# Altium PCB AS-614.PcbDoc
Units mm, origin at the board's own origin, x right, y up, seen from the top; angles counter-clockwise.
Board outline 32 x 30 mm, 4 copper layers (Top Layer, Layer 1, Layer 2, Bottom Layer), stack 0.98 mm thick; 51 components, 41 nets, 241 pads, 105 vias.
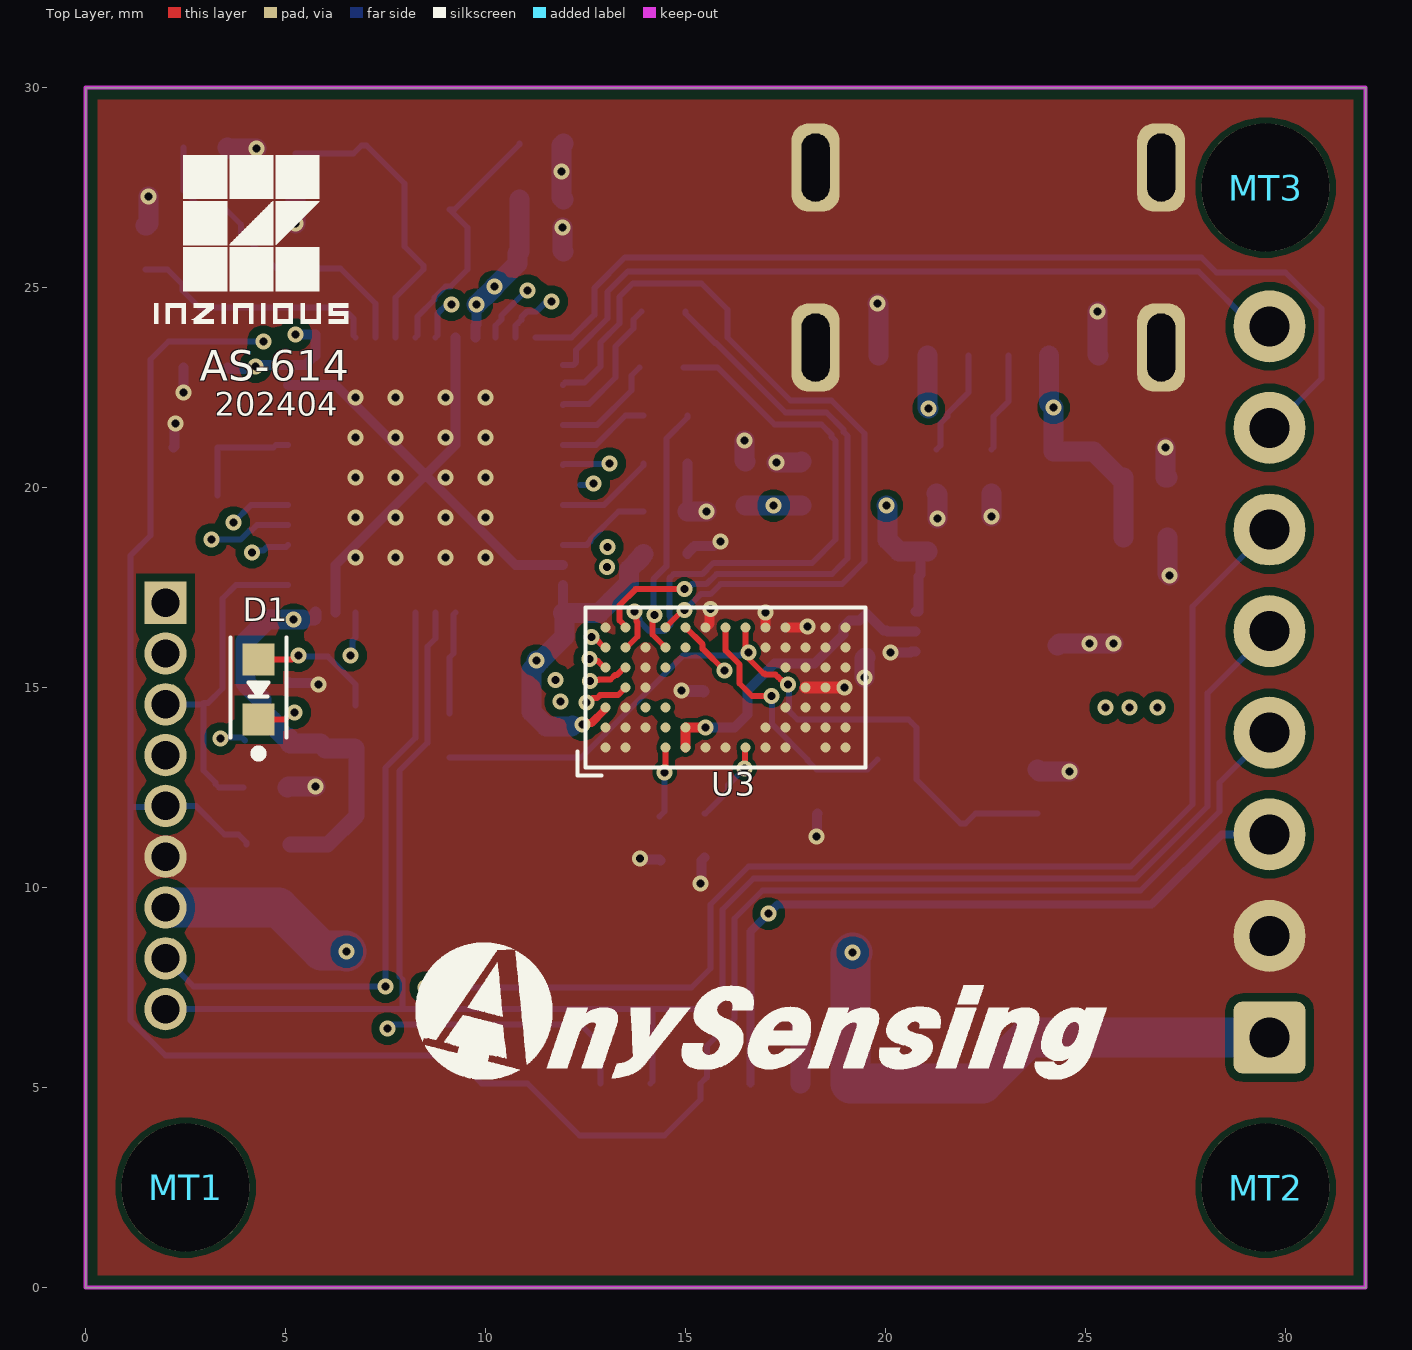
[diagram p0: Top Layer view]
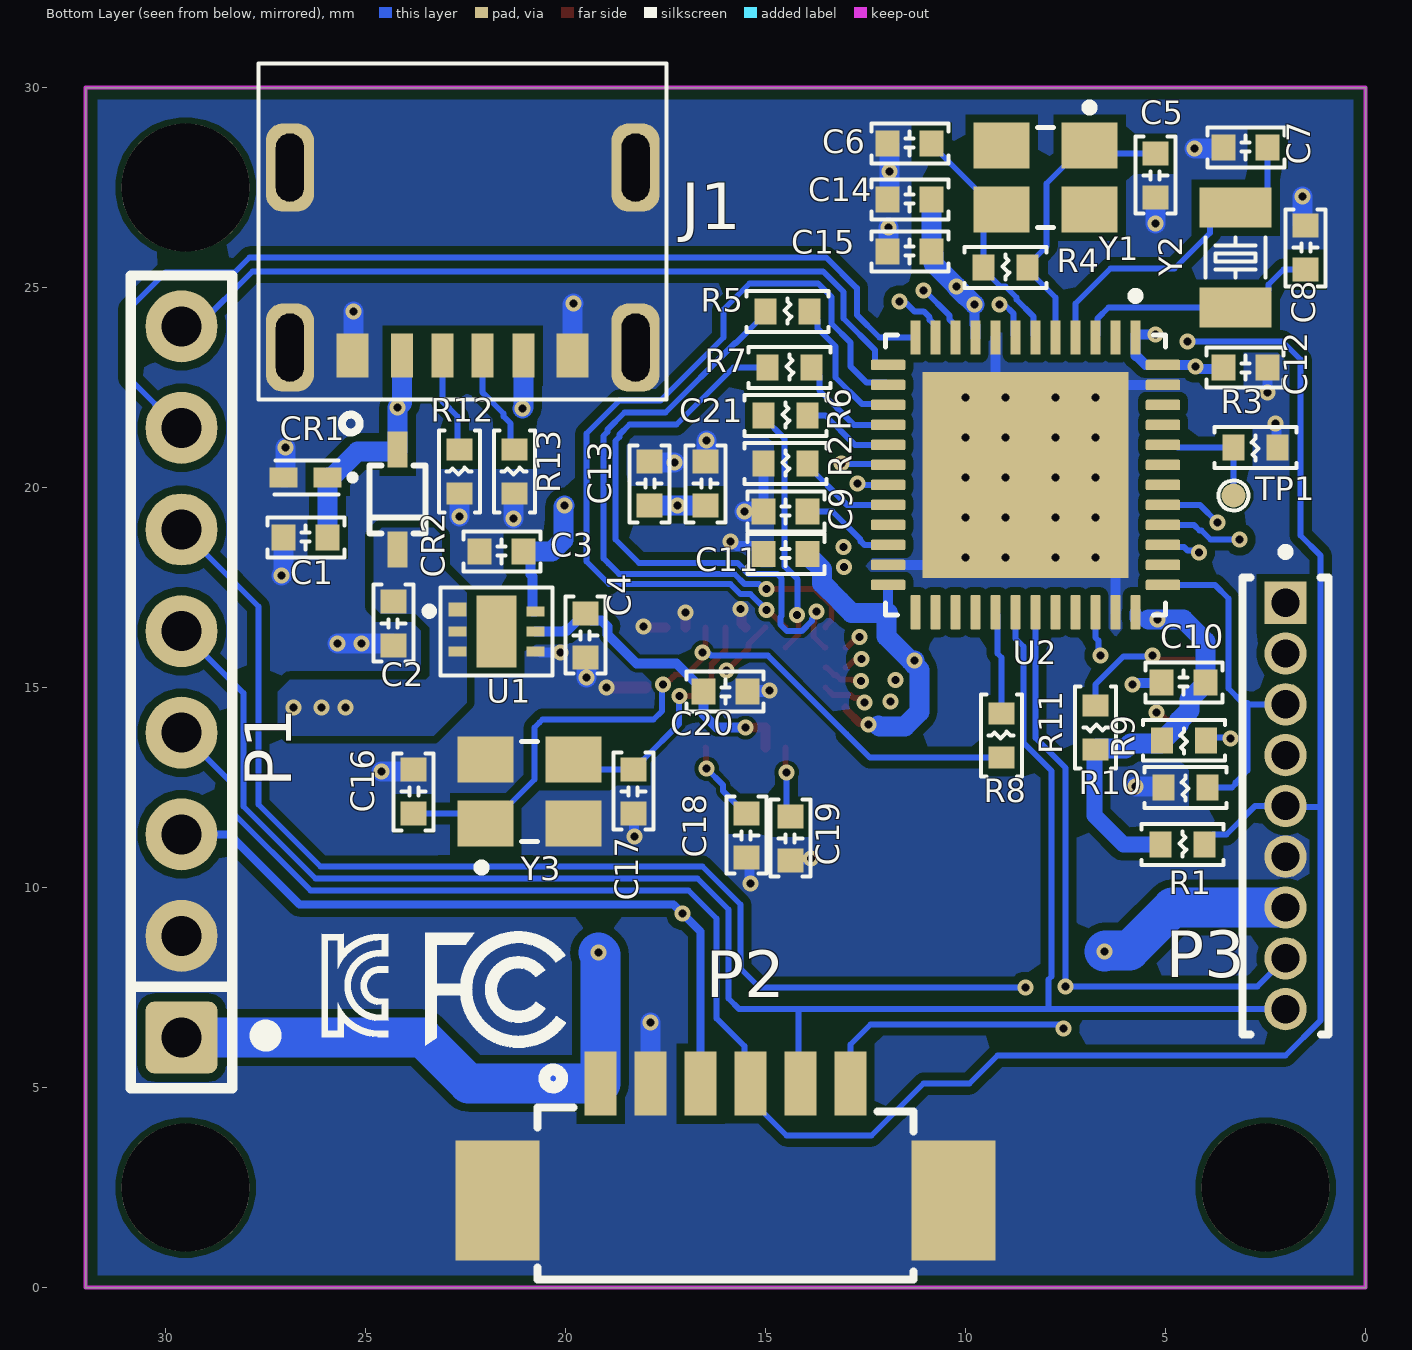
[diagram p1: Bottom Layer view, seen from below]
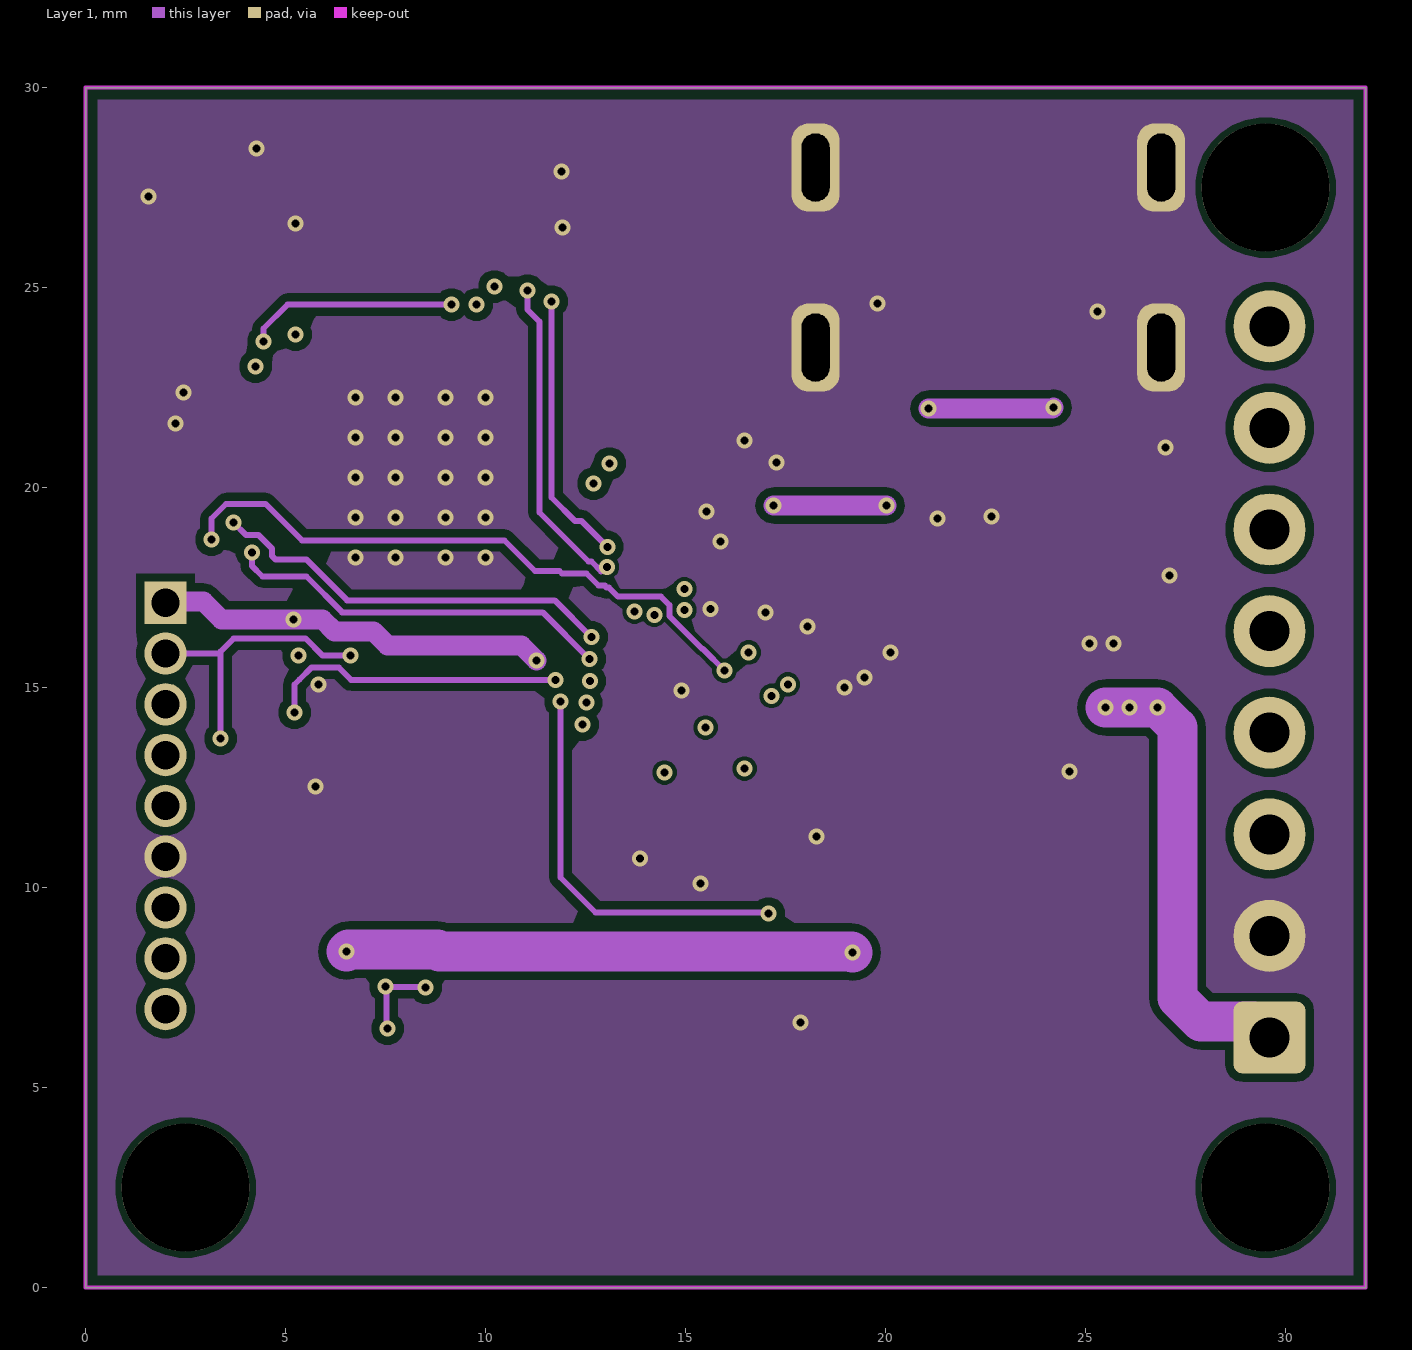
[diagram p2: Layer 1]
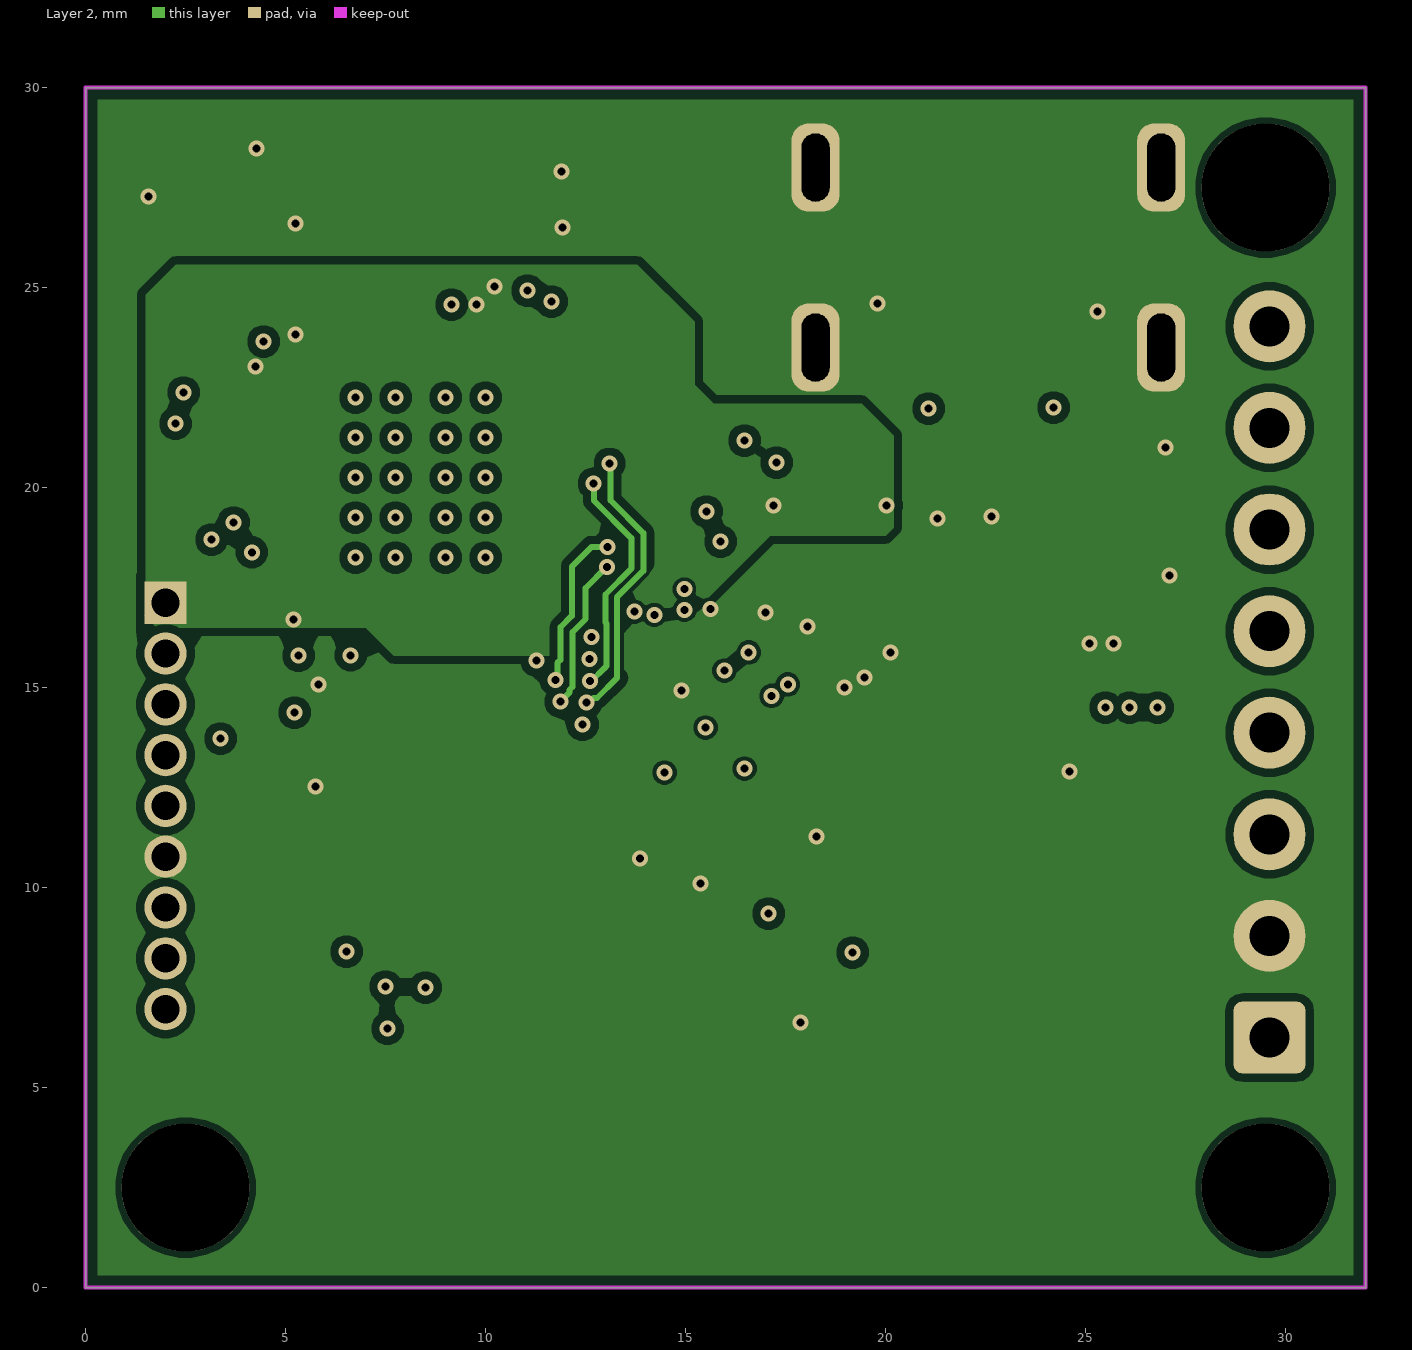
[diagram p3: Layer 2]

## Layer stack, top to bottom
Top Solder: solder mask 0.0102, Solder Resist, Dk 3.5
Top Layer: signal copper 0.0356
Dielectric 2: prepreg 0.0711, PP-006, Dk 4.1
Layer 1: signal copper 0.035
Dielectric 1: dielectric 0.697, FR-4, Dk 4.8
Layer 2: signal copper 0.035
Dielectric 3: prepreg 0.0711, PP-006, Dk 4.1
Bottom Layer: signal copper 0.0356
Bottom Solder: solder mask 0.0102, Solder Resist, Dk 3.5

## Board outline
0,0 0,30 32,30 32,0

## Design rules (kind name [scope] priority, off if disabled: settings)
AssemblyTestPointUsage [All] p1 off:
AssemblyTestpoint [All] p1 off: testpointundercomponent=TRUE minsize=1.016 maxsize=2.54 preferedsize=1.524 minholesize=0 maxholesize=1.016 preferedholesize=0.813 testpointgrid=0.025 usegrid=TRUE gridtolerance=0 allowsidetop=TRUE allowsidebottom=TRUE
BoardOutlineClearance BoardOutlineClearance_1 [OnLayer('Layer 2')] p1 off: gap=0.7 ignorepadtopadclearanceinfootprint=FALSE
BoardOutlineClearance [All] p2: gap=0.3 ignorepadtopadclearanceinfootprint=FALSE
Clearance Clearance_BGA [WithinRoom('BGA')] p1: gap=0.1 ignorepadtopadclearanceinfootprint=TRUE
Clearance [All] p2: gap=0.15 ignorepadtopadclearanceinfootprint=TRUE except(0.2: Arc-Fill Arc-Poly Arc-Region Track-Fill Track-Poly Track-Region SMDPad-Fill SMDPad-Poly SMDPad-Region THPad-Fill THPad-Poly THPad-Region Via-Fill Via-Poly Via-Region Fill-Fill Fill-Poly Fill-Region Poly-Poly Poly-Region Region-Region)
ComponentClearance [All] p1 off: gap=0.254 collisioncheckmode=3 verticalgap=0.254 showdistances=FALSE
DiffPairsRouting [All] p1: maxlimit=0.254 minlimit=0.1 mostfreqgap=0.1 toplayer_minwidth=0.17 toplayer_maxwidth=0.381 toplayer_prefwidth=0.17 midlayer1_minwidth=0.17 midlayer1_maxwidth=0.381 midlayer1_prefwidth=0.17 midlayer2_minwidth=0.17 midlayer2_maxwidth=0.381 midlayer2_prefwidth=0.17 bottomlayer_minwidth=0.17 bottomlayer_maxwidth=0.381 bottomlayer_prefwidth=0.17 maxuncoupledlength=12.7
FabricationTestPointUsage [All] p1 off: valid=0 allowmultiple=FALSE
FabricationTestpoint [All] p1 off: side=3 testpointundercomponent=TRUE minsize=1.016 maxsize=2.54 preferedsize=1.524 minholesize=0 maxholesize=1.016 preferedholesize=0.813 testpointgrid=0.025 allowsidetop=TRUE allowsidebottom=TRUE usegrid=TRUE gridtolerance=0
Height [All] p1 off: minheight=0 maxheight=25.4 prefheight=12.7
HoleSize [All] p1 off: absolutevalues=TRUE maxlimit=2.54 minlimit=0.025 maxpercent=80.000 minpercent=20.000
HoleToHoleClearance [All] p1 off: gap=0.254 allowstackedmicrovias=TRUE
LayerPairs [All] p1 off: enforce=TRUE
MinimumSolderMaskSliver [All] p1 off: minsoldermaskwidth=0.254
NetAntennae [All] p1 off: netantennaetolerance=0
PolygonConnect [All] p1: connectstyle=Direct reliefconductorwidth=0.254 reliefentries=4 polygonreliefangle="90 Angle" airgapwidth=0.254
RoomDefinition BGA [False] p1: confinementstyle=ConfineIn formatcopy=TRUE lockcomponents=FALSE outline 12.981,18.1 19,18.1 19,11.968 12.981,11.968
RoutingVias [All] p1: holewidth=0.711 width=1.27 viastyle="Through Hole" minholewidth=0.711 minwidth=1.27 maxholewidth=0.711 maxwidth=1.27 useviatemplates=TRUE viatemplateguid#1={A169AA66-EAF8-4FBB-931A-80E976BA8041} viatemplatename#1=v40h20m0mx0
SilkToSilkClearance [All] p1 off: silktosilkclearance=0.254
SilkToSolderMaskClearance [IsPad] p1 off: minsilkscreentomaskgap=0.254 clearancetoexposedcopper=TRUE
SolderMaskExpansion [All] p1: expansion=0.102 istentingtop=FALSE
SupplyNets "Schematic Supply Nets_3" [InNet('VCC_3V3')] p1: voltage=0.000
SupplyNets "Schematic Supply Nets_2" [InNet('GND')] p2: voltage=0.000
SupplyNets "Schematic Supply Nets_1" [InNet('VCC_1V8')] p3: voltage=0.000
SupplyNets "Schematic Supply Nets" [InNet('VCC_EXT')] p4: voltage=0.000
Width [All] p1: maxlimit=3 minlimit=0.15 preferedwidth=0.15
16 further rules are at their usual default settings.

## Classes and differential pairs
component class AS-614: C1 C2 C3 C4 C5 C6 C7 C8 C9 C10 C11 C12 C13 C14 C15 C16 C17 C18 C19 C20 C21 CR1 CR2 D1 J1 P1 P2 P3 R1 R2 R3 R4 R5 R6 R7 R8 R9 R10 R11 R12 R13 TP1 U1 U2 U3 Y1 Y2 Y3

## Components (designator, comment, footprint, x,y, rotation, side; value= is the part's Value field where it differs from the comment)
C1 "Cap Semi" "CAP 0402/1005" 26.5,18.75 r180 bottom value=1uF
C2 "Cap Semi" "CAP 0402/1005" 24.3,16.6 r90 bottom value=1uF
C3 "Cap Semi" "CAP 0402/1005" 21.6,18.4 r180 bottom value=1uF
C4 "Cap Semi" "CAP 0402/1005" 19.5,16.3 r90 bottom value=1uF
C5 "Cap Semi" "CAP 0402/1005" 5.25,27.8 r90 bottom value=20pF
C6 "Cap Semi" "CAP 0402/1005" 11.4,28.6 r180 bottom value=20pF
C7 "Cap Semi" "CAP 0402/1005" 3,28.5 r180 bottom value=10pF
C8 "Cap Semi" "CAP 0402/1005" 1.5,26 r270 bottom value=10pF
C9 "Cap Semi" "CAP 0402/1005" 14.5,19.4 r180 bottom value=4.7uF
C10 "Cap Semi" "CAP 0402/1005" 4.55,15.125 r180 bottom value=100nF
C11 "Cap Semi" "CAP 0402/1005" 14.495,18.333 r180 bottom value=100nF
C12 "Cap Semi" "CAP 0402/1005" 3,23 r0 bottom value=100nF
C13 "Cap Semi" "CAP 0402/1005" 17.9,20.1 r270 bottom value=4.7uF
C14 "Cap Semi" "CAP 0402/1005" 11.4,27.2 r180 bottom value=100nF
C15 "Cap Semi" "CAP 0402/1005" 11.4,25.9 r180 bottom value=1uF
C16 "Cap Semi" "CAP 0402/1005" 23.8,12.4 r270 bottom value=8pF
C17 "Cap Semi" "CAP 0402/1005" 18.3,12.4 r90 bottom value=8pF
C18 "Cap Semi" "CAP 0402/1005" 15.475,11.3 r90 bottom value=1uF
C19 "Cap Semi" "CAP 0402/1005" 14.375,11.225 r90 bottom value=1uF
C20 "Cap Semi" "CAP 0402/1005" 16,14.9 r0 bottom value=470nF
C21 "Cap Semi" "CAP 0402/1005" 16.5,20.1 r270 bottom value=220nF
CR1 "LESD5D5.0CT1G" SOD523 26.5,20.25 r180 bottom
CR2 "BAT760Q-7" "SOD-323 - 21" 24.2,19.7 r270 bottom
D1 "LED2" "LED 0603/1608 RED" 4.325,14.95 r270 top
J1 "TYPE-C-31-M-17" CON/USB-C/6P-1 22.57,23.5 r0 bottom locked
MT1 "MOUNT HOLE" "MT-3 /HOLE" 2.5,2.5 r0 top locked
MT2 "MOUNT HOLE" "MT-3 /HOLE" 29.5,2.5 r0 top
MT3 "MOUNT HOLE" "MT-3 /HOLE" 29.5,27.5 r0 top locked
P1 "EXT_IO1/2.54mm" "Pin Header 1x8 TH Pitch 2.54mm" 29.6,6.25 r90 bottom locked
P2 "EXT_IO2/12505WR-06" 12505WR-06/53261-0671 16,5.1 r180 bottom locked
P3 "Debug/1.27mm" "PIN HEADER 1X9 TH 1.27mm" 2,12.04 r270 bottom
R1 "Res3" "RES 0402/1005" 4.575,11.075 r0 bottom value=10K
R2 "Res3" "RES 0402/1005" 14.5,20.6 r0 bottom value=10K
R3 "Res3" "RES 0402/1005" 2.75,21 r180 bottom value=10K
R4 "Res3" "RES 0402/1005" 9,25.5 r0 bottom value=1M
R5 "Res3" "RES 0402/1005" 14.45,24.4 r0 bottom value=33R
R6 "Res3" "RES 0402/1005" 14.5,21.8 r0 bottom value=33R
R7 "Res3" "RES 0402/1005" 14.4,23 r0 bottom value=33R
R8 "Res3" "RES 0402/1005" 9.1,13.8 r270 bottom value=0R
R9 "Res3" "RES 0402/1005" 4.532,13.681 r180 bottom value=10K
R10 "Res3" "RES 0402/1005" 4.5,12.5 r180 bottom value=10K
R11 "Res3" "RES 0402/1005" 6.75,14 r90 bottom value=330R
R12 "Res3" "RES 0402/1005" 22.65,20.4 r270 bottom value=5.1K
R13 "Res3" "RES 0402/1005" 21.275,20.4 r270 bottom value=5.1K
TP1 "BOOT" "TP/0.6 / SMD" 3.3,19.8 r180 bottom
U1 "VRD1833MLX" "LLP-6 / L2.0-W1.8-P0.50-BL-EP" 21.725,16.425 r270 bottom
U2 "APM32F411CEU6" "VQFN-48/ QFN50P700X700X100-49N" 8.5,20.315 r270 bottom
U3 "SC1240AR3" "BGA62 7X4" 16,15 r90 top locked
Y1 "CRYSTAL13" XTAL_3225 8,27.75 r0 bottom value=8MHz
Y2 "CRYSTAL13" XTAL/3215 3.25,25.75 r270 bottom value=32.768KHz
Y3 "CRYSTAL13" XTAL_3225 20.9,12.4 r180 bottom value=40MHz

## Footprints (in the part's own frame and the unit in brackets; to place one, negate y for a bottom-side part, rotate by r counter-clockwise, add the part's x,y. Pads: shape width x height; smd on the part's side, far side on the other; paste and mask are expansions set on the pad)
12505WR-06/53261-0671 [mm]
  rect 0.8x1.6 smd: 1(-3.125,0) 2(-1.875,0) 3(-0.625,0) 4(0.625,0) 5(1.875,0) 6(3.125,0)
  rect 2.1x3 smd: H(-5.7,-2.925) H(5.7,-2.925)
  silkscreen extent -4.7,-4.9 4.7,0.35, body extent -6.39,-4.75 6.26,0.45, height 3.4
"BGA62 7X4" [mm]
  round 0.25 smd mask+0.05: A1(-1.5,3) A2(-1,3) A3(-0.5,3) A5(0.5,3) A6(1,3) A7(1.5,3) B1(-1.5,2.5) B2(-1,2.5) B3(-0.5,2.5) B4(0,2.5) B5(0.5,2.5) B6(1,2.5) B7(1.5,2.5) C2(-1,2) C3(-0.5,2) C4(0,2) C5(0.5,2) C6(1,2) D1(-1.5,1.5) D2(-1,1.5) D3(-0.5,1.5) D5(0.5,1.5) D6(1,1.5) D7(1.5,1.5) E1(-1.5,1) E2(-1,1) E6(1,1) E7(1.5,1) F1(-1.5,0.5) F7(1.5,0.5) G1(-1.5,0) G7(1.5,0) H1(-1.5,-0.5) H7(1.5,-0.5) J1(-1.5,-1) J2(-1,-1) J6(1,-1) J7(1.5,-1) K1(-1.5,-1.5) K2(-1,-1.5) K3(-0.5,-1.5) K5(0.5,-1.5) K6(1,-1.5) K7(1.5,-1.5) L2(-1,-2) L3(-0.5,-2) L4(0,-2) L5(0.5,-2) L6(1,-2) M1(-1.5,-2.5) M2(-1,-2.5) M3(-0.5,-2.5) M4(0,-2.5) M5(0.5,-2.5) M6(1,-2.5) M7(1.5,-2.5) N1(-1.5,-3) N2(-1,-3) N3(-0.5,-3) N5(0.5,-3) N6(1,-3) N7(1.5,-3)
  silkscreen extent -2.2,-3.5 2,3.7, body extent -2.02,-3.5 2,3.5, height 1.2
"CAP 0402/1005" [mm] "Chip Capacitor, 2-Leads, Body 1.02x0.51mm, IPC Medium Density"
  rect 0.6x0.65 smd: 1(-0.55,0) 2(0.55,0)
  silkscreen extent -0.95,-0.5 0.97,0.5, body extent -0.5,-0.26 0.5,0.26, height 0.52
CON/USB-C/6P-1 [mm]
  rect 0.55x1.1 smd: A5(-0.5,0.2) A9(1.52,0.2) B5(0.5,0.2) B9(-1.52,0.2)
  rect 0.8x1.1 smd: A12(2.75,0.2) B12(-2.75,0.2)
  rrect70% 1.2x2.2 hole 0.7 slot 1.7 at 90 deg: MP(-4.32,-4.5) MP(-4.32,0) MP(4.32,-4.5) MP(4.32,0)
  silkscreen extent -5.1,-7.1 5.1,2.12, body extent -4.47,-6.7 4.47,0.2, height 3.26
"LED 0603/1608 RED" [mm] "Chip Diode, 2-Leads, Body 1.60x0.80mm, IPC Medium Density"
  rect 0.8x0.8 smd: 1(-0.75,0) 2(0.75,0)
  silkscreen extent -1.3,-0.7 1.65,0.7, body extent -0.8,-0.4 0.8,0.4, height 0.53
"LLP-6 / L2.0-W1.8-P0.50-BL-EP" [mm]
  rect 0.35x0.45 smd paste+0 mask+0.051: 1(-0.525,-0.975)
  rect 0.25x0.45 smd paste+0 mask+0.051: 2(0.025,-0.975) 3(0.525,-0.975) 4(0.525,0.975) 5(0.025,0.975) 6(-0.475,0.975)
  rect 1.8x1 smd paste+0 mask+0.051: 7(0.025,0)
  silkscreen extent -1.07,-1.74 1.12,1.4, body extent -0.9,-1 0.9,1, height 0.6
"MT-3 /HOLE" [mm] "Mount Hole 4mm"
  round 3.2 hole 3.2 unplated mask+0: 1(0,0)
"Pin Header 1x8 TH Pitch 2.54mm" [mm] "PinHeader 1x8 TH Pitch 2.54mm"
  rrect25% 1.8x1.8 hole 1: 1(0,0)
  round 1.8 hole 1: 2(2.54,0) 3(5.08,0) 4(7.62,0) 5(10.16,0) 6(12.7,0) 7(15.24,0) 8(17.78,0)
  silkscreen extent -1.27,-2.25 19.05,1.27
"PIN HEADER 1X9 TH 1.27mm" [mm]
  rect 1.06x1.06 hole 0.71: 1(-5.08,0)
  round 1.06 hole 0.71: 2(-3.81,0) 3(-2.54,0) 4(-1.27,0) 5(0,0) 6(1.27,0) 7(2.54,0) 8(3.81,0) 9(5.08,0)
  silkscreen extent -6.45,-1.08 5.71,1.08
"RES 0402/1005" [mm] "Chip Resistor, 2-Leads, Body 1.0x0.5mm, IPC Medium Density"
  rect 0.55x0.65 smd: 1(-0.55,0) 2(0.55,0)
  silkscreen extent -1.02,-0.51 1.02,0.51, body extent -0.5,-0.25 0.5,0.25, height 0.35
SOD523 [mm]
  rect 0.7x0.5 smd: 1(0.55,0) 2(-0.55,0)
  silkscreen extent -0.77,-0.43 1.22,0.43, body extent -0.77,-0.4 0.83,0.4, height 0.65
"SOD-323 - 21" [mm]
  rect 0.9x0.5 smd: 1(1.25,0) 2(-1.25,0)
  silkscreen extent -0.85,-0.7 0.85,0.7, body extent -1.34,-0.66 1.34,0.64, height 1.15
"TP/0.6 / SMD" [mm]
  round 0.6 smd: 1(0,0)
  silkscreen extent -0.38,-0.38 0.37,0.38
"VQFN-48/ QFN50P700X700X100-49N" [mm]
  rrect25% 0.86x0.26 smd: 1(-3.435,2.75) 2(-3.435,2.25) 3(-3.435,1.75) 4(-3.435,1.25) 5(-3.435,0.75) 6(-3.435,0.25) 7(-3.435,-0.25) 8(-3.435,-0.75) 9(-3.435,-1.25) 10(-3.435,-1.75) 11(-3.435,-2.25) 12(-3.435,-2.75) 25(3.435,-2.75) 26(3.435,-2.25) 27(3.435,-1.75) 28(3.435,-1.25) 29(3.435,-0.75) 30(3.435,-0.25) 31(3.435,0.25) 32(3.435,0.75) 33(3.435,1.25) 34(3.435,1.75) 35(3.435,2.25) 36(3.435,2.75)
  rrect25% 0.26x0.86 smd: 13(-2.75,-3.435) 14(-2.25,-3.435) 15(-1.75,-3.435) 16(-1.25,-3.435) 17(-0.75,-3.435) 18(-0.25,-3.435) 19(0.25,-3.435) 20(0.75,-3.435) 21(1.25,-3.435) 22(1.75,-3.435) 23(2.25,-3.435) 24(2.75,-3.435) 37(2.75,3.435) 38(2.25,3.435) 39(1.75,3.435) 40(1.25,3.435) 41(0.75,3.435) 42(0.25,3.435) 43(-0.25,3.435) 44(-0.75,3.435) 45(-1.25,3.435) 46(-1.75,3.435) 47(-2.25,3.435) 48(-2.75,3.435)
  rect 5.15x5.15 smd paste-4: 49(0,0)
  silkscreen extent -4.57,-3.5 3.5,3.5, body extent -3.5,-3.5 3.5,3.5, height 1
XTAL/3215 [mm]
  rect 1x1.8 smd: 1(-1.25,0) 2(1.25,0)
  silkscreen extent -0.5,-0.75 0.5,0.75, body extent -1.6,-0.75 1.6,0.75, height 0.8
XTAL_3225 [mm]
  rect 1.4x1.15 smd: 1(-1.1,-0.8) 2(1.1,-0.8) 3(1.1,0.8) 4(-1.1,0.8)
  silkscreen extent -1.2,-1.85 0.2,1.25, body extent -1.6,-1.25 1.6,1.25, height 1

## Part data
C1 C2 C3 C4 C5 C6 C7 C8 C9 C10 C11 C12 C13 C14 C15 C16 C17 C18 C19 C20 C21: "Capacitor (Semiconductor SIM Model)"
CR1: "No Description Available", Mfr_Name="UMW(Youtai Semiconductor Co., Ltd.)"
CR2: "No Description Available", Mfr_Name="Diodes Inc"
D1: "Typical RED, GREEN, YELLOW, AMBER GaAs LED"
J1: library part CON/USB-C/6P, "6P C-type Connector"
MT1 MT2 MT3: library part "Mount Bolt"
P1: library part "Header 8", "Header, 8-Pin"
P2: library part "Header 6", "Header, 6-Pin"
P3: library part "Header 9", "Header, 9-Pin"
R1 R2 R3 R4 R5 R6 R7 R8 R9 R10 R11 R12 R13: "Resistor"
TP1: library part TP, "Test Point", Color=Red, Manufacturer=Keystone, Supplier Part Number 1=36-5010-ND

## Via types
v1: diameter 0.4, hole 0.2, Top Layer to Bottom Layer, tented both sides, 105 vias

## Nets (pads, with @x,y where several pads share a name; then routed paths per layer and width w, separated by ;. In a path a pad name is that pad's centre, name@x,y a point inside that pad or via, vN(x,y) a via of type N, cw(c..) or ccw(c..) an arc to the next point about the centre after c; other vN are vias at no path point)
GND: C1.1 C2.1 C3.1 C4.1 C5.1 C6.1 C7.1 C8.1 C9.1 C10.1 C11.1 C12.1 C13.1 C14.1 C15.1 C16.1 C17.1 C18.1 C19.1 C20.1 C21.1 CR1.2 J1.A12 J1.B12 J1.MP P1.2 P2.2 P2.H P3.6 R2.2 R3.2 R10.1 R12.2 R13.2 U1.4 U2.8 U2.23 U2.35 U2.47 U2.49 U3.A1 U3.A2 U3.A7 U3.B1 U3.B2 U3.B3 U3.C2 U3.C4 U3.C5 U3.C6 U3.F1 U3.F7 U3.G1 U3.J1 U3.J2 U3.J6 U3.J7 U3.K1 U3.K2 U3.K3 U3.K5 U3.K6 U3.K7 U3.L2 U3.L3 U3.L4 U3.L5 U3.L6 U3.M1 U3.M2 U3.M3 U3.M4 U3.M5 U3.M6 U3.M7 U3.N1 U3.N2 U3.N3 U3.N5 U3.N6 U3.N7 Y3.2 Y3.4 | length 42.7
  Top Layer w0.25: U3.F7 15.597,16.597 15.597,16.93 v1(15.625,16.958) ; U3.J7 v1(17,16.875) ; U3.K7 18.025,16.5 v1(18.05,16.525) v1@18.025,16.55
  Top Layer w0.3: U3.L4 U3.M4 v1(18.975,15)
  Bottom Layer w0.25: R3.2 2.225,21.025 2.225,21.575 v1(2.25,21.6) ; v1(2.45,22.375) C12.1 ; U2.47 6.25,22.565 U2.49 ; C10.1 5.113,15.112 5.739,15.112 5.781,15.071 v1(5.821,15.071) ; U2.35 6.25,18.065 U2.49 ; U2.8 9.25,21.065 U2.49 ; U2.23 10.75,18.065 U2.49 ; v1(13.868,10.725) 13.892,10.7 14.35,10.7 C19.1 ; C11.1 15.045,18.358 15.22,18.533 15.718,18.533 15.834,18.65 v1(15.875,18.65) ; C9.1 R2.2 ; v1(15.375,10.1) 15.404,10.129 15.404,10.679 C18.1 ; v1(18.275,11.275) 18.287,11.287 18.287,11.838 C17.1 ; v1(20.125,15.875) 20.625,15.875 20.65,15.9 U1.4
  Bottom Layer w0.3: v1(14.9,14.925) 14.913,14.913 15.438,14.913 C20.1
  Bottom Layer w0.5: C8.1 1.525,26.55 1.575,26.6 v1(1.575,27.275) ; C7.1 3.575,28.475 v1(4.275,28.475) ; R10.1 5.075,12.525 v1(5.75,12.525) ; v1(5.25,26.6) C5.1 ; v1(11.925,26.5) 11.925,25.925 C15.1 ; C14.1 11.9,27.25 11.9,28.55 C6.1 ; C9.1 v1(15.526,19.4) ; v1(16.476,21.174) 16.476,20.674 C21.1 ; v1(17.275,20.625) 17.875,20.625 C13.1 ; P2.2 v1(17.875,6.625) ; v1(19.475,15.25) 19.475,15.725 C4.1 ; v1(19.8,24.6) 19.82,24.58 J1.B12 ; R13.2 21.3,19.825 v1(21.3,19.225) ; v1(22.65,19.275) R12.2 ; C16.1 23.85,12.9 v1(24.6,12.9) ; C2.1 24.35,16.1 v1(25.1,16.1) v1(25.7,16.1) ; v1(25.3,24.4) 25.3,23.32 J1.A12 ; v1(27,21) 27,20.25 CR1.2 ; C1.1 27.05,17.85 v1(27.1,17.8)
  other v1: 6.75,18.25 7.75,18.25 9,18.25 10,18.25 6.75,19.25 7.75,19.25 9,19.25 10,19.25 6.75,20.25 7.75,20.25 9,20.25 10,20.25 6.75,21.25 7.75,21.25 9,21.25 10,21.25 6.75,22.25 7.75,22.25 9,22.25 10,22.25 11.9,27.9
NetC1_2: C1.2 CR1.1 CR2.2 J1.A9 J1.B9 | length 10.4
  Layer 1 w0.5: v1(21.075,21.975) 24.175,21.975 v1(24.2,22)
  Bottom Layer w0.5: J1.B9 21.05,22 v1(21.075,21.975) ; J1.A9 24.09,22.11 v1(24.2,22) CR2.2 24.2,20.9 25.2,20.9 25.85,20.25 CR1.1 C1.2
NetC5_2: C5.2 R4.1 U2.5 Y1.1 | length 7.5
  Bottom Layer w0.15: C5.2 6.7,28.35 Y1.1 7.025,28.55 7.975,27.6 7.975,26.025 8.45,25.55 R4.1 8.45,25.45 7.75,24.75 U2.5
NetC6_2: C6.2 R4.2 U2.6 Y1.3 | length 6.4
  Bottom Layer w0.15: U2.6 8.305,23.805 8.305,24.28 8.725,24.7 8.725,24.749 9.001,25.025 9.125,25.025 9.55,25.45 9.55,26.5 Y1.3 9.225,26.95 10.85,28.575 C6.2
NetC7_2: C7.2 U2.4 Y2.1 | length 8
  Bottom Layer w0.15: C7.2 2.45,27.425 2.875,27 3.462,27 3.887,26.575 3.887,26.363 4.775,25.475 6.375,25.475 7.25,24.6 U2.4
NetC8_2: C8.2 U2.3 Y2.2 | length 6.3
  Bottom Layer w0.15: C8.2 2.05,25.45 2.425,25.075 2.425,24.925 2.85,24.5 Y2.2 6.425,24.5 6.695,24.23 6.695,23.805 U2.3
NetC9_2: C9.2 U2.22 | length 2.4
  Bottom Layer w0.15: U2.22 12.532,18.565 12.619,18.653 12.619,18.694 13.326,19.4 C9.2
NetC16_2: C16.2 R8.2 U3.H7 Y3.1 | length 19.6
  Top Layer w0.15: U3.H7 v1@16.5,15.88 ; v1(16.58,15.88) v1@16.5,15.88 ; v1(17.557,15.079) 17.502,15.079 17.381,15.2 17.376,15.2 17.309,15.267 17.251,15.325 17,15.325 16.975,15.35 16.95,15.35 16.5,15.8 v1@16.5,15.88
  Bottom Layer w0.15: R8.2 12.392,13.25 12.981,13.839 14.942,15.8 16.367,15.8 16.399,15.832 16.532,15.832 v1(16.58,15.88) ; v1(17.557,15.079) 17.588,15.047 17.588,14.412 17.8,14.2 20.575,14.2 20.65,14.125 20.775,14 20.775,12.7 21.875,11.6 Y3.1 22.25,11.85 C16.2
NetC17_2: C17.2 U3.G7 Y3.3 | length 6.4
  Top Layer w0.15: U3.G7 16,15.929 16.349,15.58 16.349,15.101 16.662,14.788 v1(17.15,14.788)
  Bottom Layer w0.15: v1(17.15,14.788) 17.159,14.779 17.159,14.091 18.05,13.2 18.05,13.175 18.275,12.95 C17.2 19.55,12.95 Y3.3
NetC18_2: C18.2 U3.H1 | length 2.1
  Top Layer w0.15: v1(16.475,12.975) 16.487,12.988 16.487,13.487 U3.H1
  Bottom Layer w0.15: C18.2 15.5,11.85 15.618,11.968 16.059,12.409 16.059,12.559 v1(16.475,12.975)
NetC19_2: C19.2 U3.D1 | length 1.8
  Top Layer w0.15: v1(14.475,12.875) 14.5,12.9 U3.D1
  Bottom Layer w0.15: C19.2@14.35,11.775 14.475,11.9 v1(14.475,12.875)
NetD1_1: D1.1 R11.2 | length 3.3
  Top Layer w0.15: D1.1 5.157,15.7 5.257,15.8 v1(5.325,15.8)
  Bottom Layer w0.15: v1(5.325,15.8) 5.35,15.775 6.057,15.775 6.75,15.082 R11.2
NetD1_2: D1.2 U2.11 | length 20.9
  Top Layer w0.15: D1.2 4.982,14.2 5.157,14.375 v1(5.225,14.375)
  Layer 1 w0.15: v1(5.225,14.375) 5.225,15.075 5.35,15.2 5.645,15.496 6.336,15.496 6.638,15.194 v1(11.75,15.194) ; v1(11.65,24.65) 11.65,19.75 12.242,19.158 12.405,19.158 v1(13.044,18.518)
  Layer 2 w0.15: v1(11.75,15.194) 11.797,15.241 11.797,15.616 11.875,15.694 11.875,16.51 12.157,16.792 12.157,18.019 12.655,18.518 v1(13.044,18.518)
  Bottom Layer w0.15: U2.11 10.75,24.05 10.805,24.105 10.807,24.105 10.895,24.193 10.895,24.254 11.046,24.405 11.28,24.405 11.477,24.602 11.602,24.602 v1(11.65,24.65)
NetJ1_A5: J1.A5 R13.1 | length 2.7
  Bottom Layer w0.15: R13.1 21.375,21.05 21.375,21.603 21.55,21.778 21.55,21.85 22.07,22.37 J1.A5
NetJ1_B5: J1.B5 R12.1 | length 2.5
  Bottom Layer w0.15: R12.1 22.7,21 22.7,21.775 23.07,22.145 J1.B5
NetP1_3: P1.3 P2.3 U2.10 | length 41.1
  Layer 1 w0.15: v1(11.05,24.925) 11.05,24.448 11.35,24.148 11.35,19.375 12.575,18.15 12.649,18.15 12.892,17.907 13.003,18.018 v1(13.035,18.018) ; v1(11.875,14.65) 11.875,10.25 12.75,9.375 17.05,9.375 v1(17.075,9.35)
  Layer 2 w0.15: v1(11.875,14.65) 12.095,14.87 12.095,14.938 12.175,15.017 12.175,16.386 12.5,16.711 12.5,17.483 v1(13.035,18.018)
  Bottom Layer w0.15: U2.10 10.25,24.05 10.395,24.195 10.395,24.295 11.025,24.925 v1(11.05,24.925)
  Bottom Layer w0.203: P2.3 16.625,8.9 17.3,9.575 26.65,9.575 28.405,11.33 P1.3
NetP1_4: P1.4 P2.4 P3.5 R1.1 U2.7 | length 65.8
  Layer 1 w0.15: v1(4.45,23.65) 4.45,23.975 5.049,24.574 v1(9.151,24.574)
  Bottom Layer w0.15: 1.128,12.04 1.128,18.303 1.625,18.8 1.625,23.2 2.075,23.65 v1(4.45,23.65) ; R1.1 4.025,11.125 3.825,11.325 3.475,11.325 2.76,12.04 P3.5 1.978,12.018 1.128,12.018 1.128,6.672 2,5.8 9.2,5.8 9.9,5.1 11.05,5.1 12.35,3.8 14.475,3.8 15.375,4.7 P2.4 15.531,5.256 15.531,6.037 16.225,6.731 16.225,9.225 16.925,9.925 26.374,9.925 28.35,11.901 28.35,12.62 P1.4 ; U2.7 8.805,23.805 8.805,24.356 9.025,24.576 9.149,24.576 v1(9.151,24.574)
NetP1_5: P1.5 P2.5 P3.9 U2.30 | length 46.7
  Bottom Layer w0.15: P3.9 7.925,6.96 ; U2.30 8.75,16.225 8.55,16.025 8.55,13.982 8.55,13.618 7.85,12.918 7.85,7.776 7.925,7.701 7.925,6.96 ; P2.5 14.175,5.15 14.175,6.9 14.175,6.96 ; P1.5 28.05,14.86 28.05,12.026 26.249,10.225 16.7,10.225 15.925,9.45 15.925,7.225 15.66,6.96 14.175,6.96 ; 7.925,6.96 14.175,6.96
NetP1_6: P1.6 P2.6 P3.8 U2.31 | length 53.8
  Top Layer w0.15: v1(7.5,7.525) v1@7.55,7.475
  Layer 1 w0.15: v1(7.55,6.475) 7.525,6.5 7.525,7.5 v1(7.5,7.525) 7.512,7.512 8.488,7.512 v1(8.5,7.5)
  Bottom Layer w0.15: P3.8 2.705,7.525 v1(7.5,7.525) 7.5,12.992 8.25,13.742 U2.31 ; v1(7.55,6.475) 7.65,6.575 12.375,6.575 12.875,6.075 P2.6 ; v1(8.5,7.5) 15.15,7.5 15.625,7.975 15.625,9.574 16.576,10.525 26.125,10.525 27.675,12.075 27.675,17.025 P1.6
NetP1_7: P1.7 U2.12 | length 25
  Bottom Layer w0.15: U2.12 12.151,23.75 12.719,24.318 12.719,24.986 13.483,25.75 27.899,25.75 28.274,25.375 30,25.375 30.9,24.475 30.9,22.725 29.665,21.49 P1.7
NetP1_8: P1.8 U2.13 | length 19.8
  Bottom Layer w0.15: U2.13 12.203,23.065 12.258,23.12 12.258,23.433 13.05,24.225 13.05,24.892 13.558,25.4 27.825,25.4 29.195,24.03 P1.8
NetP3_2: P3.2 R9.2 U2.34 | length 8.9
  Layer 1 w0.15: P3.2 3.328,15.85 3.703,16.225 5.501,16.225 5.921,15.805 v1(6.628,15.805) ; v1(3.375,13.725) 3.375,15.897
  Bottom Layer w0.15: v1(3.375,13.725) 3.4,13.75 3.913,13.75 R9.2 ; v1(6.628,15.805) 6.675,15.853 6.675,16.174 6.75,16.248 U2.34
NetP3_3: P3.3 R10.2 U2.37 | length 8.5
  Bottom Layer w0.15: P3.3 2.95,14.58 2.95,12.925 3.25,12.625 3.25,12.588 3.338,12.5 R10.2 ; 2.95,14.617 3.067,14.617 3.425,14.975 3.425,17.225 3.765,17.565 U2.37
NetR2_1: R2.1 U2.20 | length 2.5
  Bottom Layer w0.15: U2.20 12.965,19.565 13.95,20.55 R2.1
NetR3_1: R3.1 TP1.1 U2.44 | length 3
  Bottom Layer w0.15: TP1.1 R3.1 4.7,21 4.765,21.065 U2.44
NetR5_1: R5.1 U2.15 | length 3.5
  Bottom Layer w0.15: U2.15 11.96,22.09 12.59,22.09 13.25,22.75 13.25,23.531 13.7,23.981 13.7,24.2 R5.1
NetR5_2: R5.2 U3.B7 | length 15.3
  Top Layer w0.15: U3.B7 13.5,16.527 13.35,16.677 13.35,17.055 13.753,17.458 v1(14.971,17.458)
  Bottom Layer w0.15: v1(14.971,17.458) 15.039,17.458 15.164,17.583 15.521,17.583 15.777,17.839 18.661,17.839 18.922,18.1 19.05,18.228 19.05,21.292 18.954,21.388 18.954,21.446 18.525,21.875 17.5,21.875 15.766,23.609 15.741,23.609 15,24.35 R5.2
NetR6_1: R6.1 U2.17 | length 2.3
  Bottom Layer w0.15: U2.17 12.765,21.065 13.5,21.8 R6.1
NetR6_2: R6.2 U3.D6 | length 6.3
  Top Layer w0.15: v1(14.218,16.818) 14.175,16.775 14.175,16.325 U3.D6
  Bottom Layer w0.15: v1(14.218,16.818) 14.195,16.842 14.195,17.704 14.52,18.029 14.52,21.22 15.05,21.75 R6.2
NetR7_1: R7.1 U2.16 | length 2.7
  Bottom Layer w0.15: U2.16 12.79,21.565 13.65,22.425 13.65,22.8 R7.1
NetR7_2: R7.2 U3.B6 | length 15.1
  Top Layer w0.15: U3.B6 13.525,16 13.8,16.275 13.8,16.624 13.773,16.651 13.773,16.852 v1(13.725,16.9)
  Bottom Layer w0.15: v1(13.725,16.9) 13.725,16.832 13.843,16.714 13.843,16.663 14.095,16.412 14.463,16.412 14.625,16.573 14.625,16.758 14.596,16.787 14.596,17.731 14.699,17.833 15.155,17.833 15.417,17.833 15.684,18.1 15.698,18.114 18.164,18.114 18.75,18.7 18.75,21.167 18.654,21.263 18.654,21.322 18.401,21.575 17.226,21.575 15.801,23 R7.2
NetR8_1: R8.1 U2.29 | length 2.6
  Bottom Layer w0.15: R8.1 9.1,15.75 9.2,15.85 9.2,16.83 U2.29
NetU2_14: U2.14 U3.D7 | length 20.2
  Top Layer w0.15: U3.D7 14.875,16.875 14.904,16.875 v1(14.971,16.943)
  Bottom Layer w0.15: U2.14 11.99,22.62 12.47,22.62 12.873,23.023 12.873,23.623 13.35,24.101 13.35,24.768 13.682,25.1 15.4,25.1 16.05,24.45 16.05,23.749 17.624,22.175 18.649,22.175 19.475,21.349 19.475,18.15 18.914,17.589 15.88,17.589 15.625,17.333 15.377,17.333 14.986,16.943 v1(14.971,16.943)
NetU2_18: U2.18 U3.B4 | length 9.1
  Top Layer w0.15: v1@12.675,14.737 12.791,14.737 12.865,14.811 12.981,14.811 13.311,14.811 U3.B4
  Layer 2 w0.15: v1(12.52,14.619) 12.588,14.619 12.705,14.737 12.786,14.737 13.282,15.233 13.282,17.253 13.945,17.916 13.945,18.1 13.945,18.86 13.125,19.68 13.125,20.575 v1(13.1,20.6)
  Bottom Layer w0.15: U2.18 11.952,20.582 13.082,20.582 v1(13.1,20.6)
NetU2_19: U2.19 U3.B5 | length 7.2
  Top Layer w0.15: v1(12.61,15.162) 12.641,15.193 12.825,15.193 12.832,15.2 13.124,15.2 13.24,15.316 13.289,15.316 13.473,15.5 U3.B5
  Layer 2 w0.15: v1(12.61,15.162) 12.651,15.162 12.981,15.493 12.981,15.5 13.025,15.543 13.025,16.6 13,16.625 13,17.325 13.645,17.97 13.645,18.736 12.706,19.675 12.706,20.094 v1(12.7,20.1)
  Bottom Layer w0.15: 12.365,20.065 12.665,20.065 v1(12.7,20.1)
NetU2_39: U2.39 U3.A5 | length 11.2
  Top Layer w0.15: v1(12.6,15.712) 12.647,15.664 12.809,15.664 12.973,15.5 12.981,15.5 U3.A5
  Layer 1 w0.15: v1(4.158,18.382) 4.158,18.042 4.425,17.775 5.523,17.775 6.418,16.88 11.428,16.88 12.596,15.712 v1(12.6,15.712)
  Bottom Layer w0.15: v1(4.158,18.382) 4.205,18.429 4.454,18.429 4.535,18.51 5.01,18.51 U2.39
NetU2_40: U2.40 U3.E7 | length 18.9
  Top Layer w0.15: U3.E7 15.01,16.5 15.43,16.079 15.43,15.968 v1(15.974,15.425)
  Layer 1 w0.15: v1(3.15,18.7) 3.15,19.226 3.512,19.588 4.501,19.588 5.414,18.675 10.475,18.675 11.238,17.912 11.85,17.912 11.912,17.85 12.524,17.85 12.824,17.55 12.981,17.55 12.981,17.541 13.023,17.5 13.085,17.5 13.31,17.275 14.385,17.275 14.596,17.064 14.596,16.787 15.425,15.959 15.44,15.959 v1(15.974,15.425)
  Bottom Layer w0.15: v1(3.15,18.7) 3.876,18.7 4.101,18.925 4.15,18.925 4.29,19.065 U2.40
NetU2_41: U2.41 U3.A6 | length 12.3
  Top Layer w0.15: v1(12.65,16.26) 12.713,16.26 12.973,16 12.981,16 U3.A6
  Layer 1 w0.15: v1(3.7,19.125) 4.008,18.817 4.323,18.817 4.667,18.473 4.667,18.283 4.755,18.195 5.528,18.195 6.543,17.18 11.729,17.18 v1(12.65,16.26)
  Bottom Layer w0.15: v1(3.7,19.125) 4.14,19.565 U2.41
VCC_1V8: C4.2 C20.2 U1.5 U3.E1 U3.E2 | length 8.1
  Top Layer w0.25: U3.E1 U3.E2 v1(15.5,14)
  Bottom Layer w0.25: v1(15.5,14) 16.225,14 16.55,14.325 C20.2 16.55,14.925 17.225,15.6 18.225,15.6 18.95,16.325 18.95,16.529 19,16.579 19.096,16.675 19.35,16.675 19.525,16.85 19.95,16.425 20.025,16.425 20.05,16.4 U1.5
VCC_3V3: C3.2 C10.2 C11.2 C12.2 C13.2 C14.2 C15.2 C21.2 P3.1 R1.2 R9.1 R11.1 U1.6 U2.1 U2.9 U2.24 U2.36 U2.48 U3.A3 | length 43.9
  Top Layer w0.2: v1(12.425,14.075) 12.463,14.113 12.65,14.113 12.97,14.433 12.97,14.456 13,14.486 U3.A3
  Layer 1 w0.5: P3.1 2.03,17.15 2.95,17.15 3.4,16.7 5.926,16.7 6.221,16.405 7.197,16.405 7.552,16.05 10.9,16.05 v1(11.275,15.675) ; v1(17.2,19.55) v1(20.025,19.55)
  Bottom Layer w0.25: C12.2 3.59,22.96 4.144,22.96 4.209,23.025 4.291,23.025 4.326,23.06 5.06,23.06 U2.48 5.495,23.065 5.718,23.287 5.75,23.287 U2.1 5.75,23.82 5.745,23.825 v1(5.25,23.825) ; U2.9 9.75,24.05 9.775,24.075 v1(9.775,24.575) ; 11.935,16.865 U2.24 ; U1.6 20.825,16.9 20.825,17.775 20.875,17.825 20.875,18.225 C3.2
  Bottom Layer w0.3: 5.425,16.7 5.73,16.7 5.75,16.72 U2.36 ; C21.2@16.475,19.55 C21.2
  Bottom Layer w0.4: R1.2 6.05,11.075 6.775,11.8 6.775,13.425 R11.1 R11.1@6.725,13.475
  Bottom Layer w0.5: 5.425,16.7 v1(5.2,16.7) 4.55,16.7 4,16.15 C10.2 4.05,15.075 4.05,15.05 4.4,14.7 4.4,14.429 4.657,14.171 4.657,14.094 4.996,13.756 5.057,13.756 5.107,13.706 5.107,13.606 5.869,13.606 6,13.475 R11.1@6.725,13.475 ; v1(9.775,24.575) 9.975,24.775 9.991,24.775 10.225,25.009 v1(10.225,25.025) 10.8,25.6 10.8,25.85 C15.2 C14.2 ; 11.935,16.865 12.846,16.865 13.139,17.158 13.139,17.161 13.585,17.606 13.585,17.949 13.895,18.258 13.895,18.283 C11.2 ; 12,16.8 11.975,16.775 11.975,16.275 11.375,15.675 v1(11.275,15.675) 11.275,15.568 11.15,15.442 11.15,14.392 11.518,14.024 12.149,14.024 12.175,14.05 ; C21.2 v1(17.2,19.55) C13.2 ; v1(20.025,19.55) 20.05,19.525 20.05,18.693 20.343,18.4 C3.2
  other v1: 4.25,23.025
VCC_EXT: C2.2 CR2.1 P1.1 P2.1 P3.7 U1.1 U1.2 U1.3 | length 43.4
  Layer 1 w1: v1(6.525,8.4) 6.575,8.45 8.802,8.45 8.852,8.4 19.15,8.4 v1(19.175,8.375) ; v1(25.5,14.5) v1(26.1,14.5) v1(26.8,14.5) 27.3,14 27.3,7.236 27.886,6.65 29.2,6.65 P1.1
  Bottom Layer w1: P3.7 4.825,9.5 5.9,8.425 6.5,8.425 v1(6.525,8.4) ; v1(19.175,8.375) 19.125,8.325 P2.1 22.425,5.1 23.575,6.25 P1.1
pads on no net: MT1.1 MT2.1 MT3.1 P3.4 U1.7 U2.2 U2.21 U2.25 U2.26 U2.27 U2.28 U2.32 U2.33 U2.38 U2.42 U2.43 U2.45 U2.46 U3.C3 U3.D2 U3.D3 U3.D5 U3.E6 Y1.2 Y1.4

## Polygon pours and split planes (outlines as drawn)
GND on Bottom Layer "GND_L04_P006" (solid, pour order 6): 0,0 0,30 32,30 32,0
VCC_EXT on Bottom Layer "NONET_L-01_P-001" (solid, pour order 1): 23.4,15.7 23.4,15.3 23.5,15.2 26.9,15.2 27.2,14.9 27.2,14.1 26.9,13.8 23.3,13.8 22.475,14.625 22.475,15.9 23.2,15.9
VCC_EXT on Bottom Layer "NONET_L-01_P-001" (solid, pour order 0): 22.475,15.775 22.475,17.375 23.1,18 23.1,18.8 23.3,19 24.6,19 24.8,18.8 24.8,17.025 24.625,16.85 23.75,16.85 23.4,16.5 23.4,15.7 23.2,15.5 22.5,15.5
GND on Layer 2 "GND_L03_P005" (solid, pour order 5): 0,0 0,30 32,30 32,0
VCC_3V3 on Layer 2 "NONET_L-01_P-001" (solid, pour order 2): 1.5,24.825 1.5,23.8 1.5,16.838 1.47,16.808 1.778,16.5 7,16.5 7.7,15.8 14.123,15.8 17.123,18.8 20,18.8 20.2,19 20.2,21.3 19.4,22.1 15.7,22.1 15.225,22.575 15.225,24.149 13.799,25.575 2.25,25.575 1.825,25.15
GND on Top Layer "GND_L01_P003" (solid, pour order 3): 0,0 0,30 32,30 32,0
GND on Layer 1 "GND_L02_P004" (solid, pour order 4): 0,0 0,30 32,30 32,0

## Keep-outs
Keep-Out Layer:
  the board outline again, w0.1

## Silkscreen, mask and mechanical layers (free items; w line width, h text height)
Top Overlay:
  drawing of 3557 lines, arcs and shapes, not listed
  text "AS-614" at 2.859,22.422 h1.3
  text "202404" at 3.227,21.595 h1
Bottom Overlay:
  drawing of 3 lines, arcs and shapes, not listed
Dimensions:
  text "Layer : 4L" at 10.1,40.558 h3
  text "Thickiness : 1.0mm" at 9.9,37.031 h3

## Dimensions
32,30 to 32,0 on Dimensions
0,30 to 32,30 on Dimensions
